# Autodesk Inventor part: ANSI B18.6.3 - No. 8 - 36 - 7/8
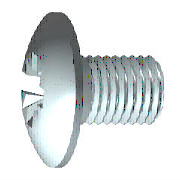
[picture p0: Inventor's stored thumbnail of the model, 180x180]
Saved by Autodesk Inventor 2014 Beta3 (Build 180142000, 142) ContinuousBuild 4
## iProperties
IsCustomPart: 0
Created: 2010-12
Part Number: ANSI B18.6.3 - No. 8 - 36 - 7/8
Material: Steel, Mild
Description: Cross Recessed Truss Head Machine Screw - Type IA
Document SubType Name: Modeling
Standard: ANSI B18.6.3
Designer: Beta-8540w
Standard Revision: 2003
Standards Organization: ANSI
Language: en-US
Size Designation: No. 8 - 36 - 7/8
Categories: <MemberInstance><Categories><Category DisplayName="Fasteners" InternalName="e4da775c-781d-43d5-af7c-5136215cf5a6" Mnemonic="FSTN"><Category DisplayName="Bolts"
Density: 1 g/cm^3
Appearance: Steel
Author: Beta-8540w
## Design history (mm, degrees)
body "Solid1"
workplane "Work Plane3"
sketch "Sketch4"
  geometry: L1 (-9, 0)-(9, 0) reference; L2 (0, -9)-(0, 9) reference; L3 (0, 0)-(6.428, 6.428); L4 (0, 0)-(6.428, -6.428); L5 (0, 0)-(-6.428, 6.428); L6 (0, 0)-(-6.428, -6.428); L7 (1.392, 1.392)-(0, 0.26); L8 (-1.392, 1.392)-(-0.26, 0); L9 (-1.392, -1.392)-(0, -0.26); L10 (1.392, -1.392)-(0.26, 0); L11 (1.392, 1.392)-(0.26, 0); L12 (-1.392, 1.392)-(0, 0.26); L13 (-1.392, -1.392)-(-0.26, 0); L14 (1.392, -1.392)-(0, -0.26); C1 r 4.877 at (0, 0) reference; A1 r 0.26 centre (0, 0) between (0, 0.26) and (0, -0.26); A2 r 1.968 centre (0, 0) between (1.392, 1.392) and (1.392, -1.392); 1 further point
  constraints: 25 end point, 7 point on circle, 7 point on line, 3 symmetric about line, 2 centre point, 2 coincident, 2 perpendicular, 3 other
  dimensions: "d11" = 0.5207 diameter of A1 (= 0.5 x SBR); "d14" = 45 deg angle of L3 L1; "d29" = 1.39194 distance from line of L1 L7.start (= 0.353553 x SDM)
extrude "Star Cut" cut sketch "Sketch4" distance "d12" = 2.5908 (= KOH); taper "d13" = -30 deg
sketch "Sketch2"
  geometry: L1 (-7.196, 0)-(9.04, 0) reference; L2 (0, -7.196)-(0, 9.04) reference; L3 (0, 1.969)-(0, 0); L4 (0, 0)-(1.968, 0); L5 (0, 0)-(6.721, 6.721); L6 (0.521, 1.898)-(0.297, 0.938); L7 (1.898, 0.521)-(0.938, 0.297); L8 (1.898, -0.521)-(0.938, -0.297); L9 (0.521, -1.898)-(0.297, -0.938); L10 (-0.521, 1.898)-(-0.297, 0.938); L11 (-1.898, 0.521)-(-0.938, 0.297); L12 (-0.521, -1.898)-(-0.297, -0.938); L13 (-1.898, -0.521)-(-0.938, -0.297); C1 r 4.877 at (0, 0) reference; A1 r 0.787 centre (0, 0) between (0.787, 0) and (0, 0.787); A2 r 0.245 centre (0.536, 0.883) between (0.297, 0.938) and (0.709, 0.709); A3 r 0.245 centre (0.883, 0.536) between (0.709, 0.709) and (0.938, 0.297); A4 r 1.968 centre (0, 0) between (1.968, 0) and (1.898, 0.521); A5 r 1.968 centre (0, 0) between (0.521, 1.898) and (0, 1.969); A6 r 1.968 centre (0, 0) between (1.898, 0.521) and (0.521, 1.898); A7 r 1.968 centre (0, 0) between (0, -1.969) and (0.521, -1.898); A8 r 1.968 centre (0, 0) between (0.521, -1.898) and (1.898, -0.521); A9 r 1.968 centre (0, 0) between (1.898, -0.521) and (1.968, 0); A10 r 0.245 centre (0.536, -0.883) between (0.709, -0.709) and (0.297, -0.938); A11 r 0.245 centre (0.883, -0.536) between (0.938, -0.297) and (0.709, -0.709); A12 r 0.245 centre (-0.536, 0.883) between (-0.709, 0.709) and (-0.297, 0.938); A13 r 0.245 centre (-0.883, 0.536) between (-0.938, 0.297) and (-0.709, 0.709); A14 r 1.968 centre (0, 0) between (-1.898, 0.521) and (-1.968, 0); A15 r 1.968 centre (0, 0) between (-0.521, 1.898) and (-1.898, 0.521); A16 r 1.968 centre (0, 0) between (0, 1.969) and (-0.521, 1.898); A17 r 1.968 centre (0, 0) between (-1.968, 0) and (-1.898, -0.521); A18 r 1.968 centre (0, 0) between (-1.898, -0.521) and (-0.521, -1.898); A19 r 1.968 centre (0, 0) between (-0.521, -1.898) and (0, -1.969); A20 r 0.245 centre (-0.883, -0.536) between (-0.709, -0.709) and (-0.938, -0.297); A21 r 0.245 centre (-0.536, -0.883) between (-0.297, -0.938) and (-0.709, -0.709); A22 r 0.984 centre (0, 0) between (0.984, 0) and (0, 0.984)
  constraints: 46 point on circle, 25 symmetric about line, 22 centre point, 22 end point, 6 tangent, 4 coincident, 3 collinear, 3 point on line, 1 midpoint, 1 perpendicular, 22 other
  dimensions: "d4" = 45 deg angle of L5 L4; "d5" = 1.5748 diameter of A1 (= 0.4 x SDM); "d6" = 3.937 diameter of A6 (= SDM); "d7" = 0.5207 distance from line of L6.start L3 (= 0.5 x SBR); "d20" = 1.9685 diameter of A22 (= 0.5 x SDM)
extrude "Slot" join sketch "Sketch2" taper "d21" = 0 deg; stored distance "d54" = 10
revolve "Cut" stored, may be unused: angle "d56" = 90 deg
revolve "Body" stored, may be unused: angle "d18" = 90 deg
node "IDS_WORKPLANE{1}"
sketch "Sketch1"
  geometry: L1 (22.225, 0)-(22.225, 2.083); L2 (22.225, 2.083)-(0, 2.083); L3 (3.962, 5.08)-(3.962, 5.08); L4 (-2.591, 0)-(-2.591, 4.877); L5 (-2.324, 1.836)-(-1.077, 1.214); L6 (-1.077, 1.214)-(-0.432, 0); L7 (-0.432, 0)-(22.225, 0); L8 (-8.191, 0)-(27.294, 0) reference; L9 (0, -1.024)-(0, 6.143) reference; L10 (-2.324, 1.836)-(-2.591, 1.968); L11 (-0.363, 4.877)-(-2.591, 4.877); L12 (-0.363, 4.877)-(0, 4.877); L13 (0, 4.877)-(0, 2.083); A1 r 6.452 centre (3.861, 0) between (-0.363, 4.877) and (-2.591, 0)
  constraints: 22 end point, 4 collinear, 4 point on circle, 3 point on line, 2 parallel, 2 perpendicular, 1 centre point, 1 horizontal, 1 tangent
  dimensions: "d1" = 4.1656 diameter of L2 L7 (= GD); "d2" = 2.159 distance from line of L6.end L4 (= STI); "d16" = 3.937 diameter of L10.end L7 (= SDM); "d17" = 62 deg angle of L6 L7; "d19" = 26.5 deg angle of L5 L7; "d23" = 9.7536 diameter of L12.end L7 (= KOD); "d25" = 2.5908 distance between parallel lines of L4 L13 (= KOH); "d26" = 6.4516 radius of A1 (= KR); "d28" = 22.225 distance between parallel lines of L1 L13 (= NLG)
fillet "Fillet1" dims "d22" = 0.20828 (= 0.2 x SBR)
feature "Thread" dims "d8" = 20.46122 (= GEL), "d9" = 0
chamfer "Chamfer" distance "d78" = 0.35278 (= 0.5 x RR); stored, may be unused: second distance "d79" = 2, angle "d80" = 45 deg
other parameters: "GD" = 4.1656 (= NND) [user parameter; used in 1 equation term], "NLG" = 22.225 [user parameter; used in 1 equation term], "GEL" = 20.46122 [user parameter; used in 1 equation term], "KOD" = 9.7536 [user parameter; used in 1 equation term], "KOH" = 2.5908 [user parameter; used in 3 equation terms], "SDM" = 3.937 [user parameter; used in 5 equation terms], "STI" = 2.159 [user parameter; used in 1 equation term], "SBR" = 1.0414 [user parameter; used in 3 equation terms], "d3" = -2.5908 (= -KOH), "d10" = 0, "KR" = 6.4516 [user parameter; used in 1 equation term], "d75" = 0, "d76" = 0, "RR" = 0.70556 (computed from TPU) [user parameter; used in 1 equation term], "GUL" = 0 [user parameter], "SPD" = 3.40106 [user parameter], "PTC" = 0.70556 (computed from TPU) [user parameter], "THREADDIA" = 4.1656 [user parameter], "TOA" = 30 deg [user parameter], "BDM" = 4.1656 (= NND) [user parameter], "NND" = 4.1656 [user parameter; used in 2 equation terms], "GAL" = 0.70612 [user parameter], "GD1" = 3.40106 [user parameter]
